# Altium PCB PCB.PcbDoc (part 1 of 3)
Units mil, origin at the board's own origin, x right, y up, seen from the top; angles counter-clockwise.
Board outline 3613 x 4415 mil, 2 copper layers (Top Layer, Bottom Layer), stack 62 mil thick; 332 components, 200 nets, 890 pads, 1069 vias.
Unrouted connection lines stored in the file: 1.
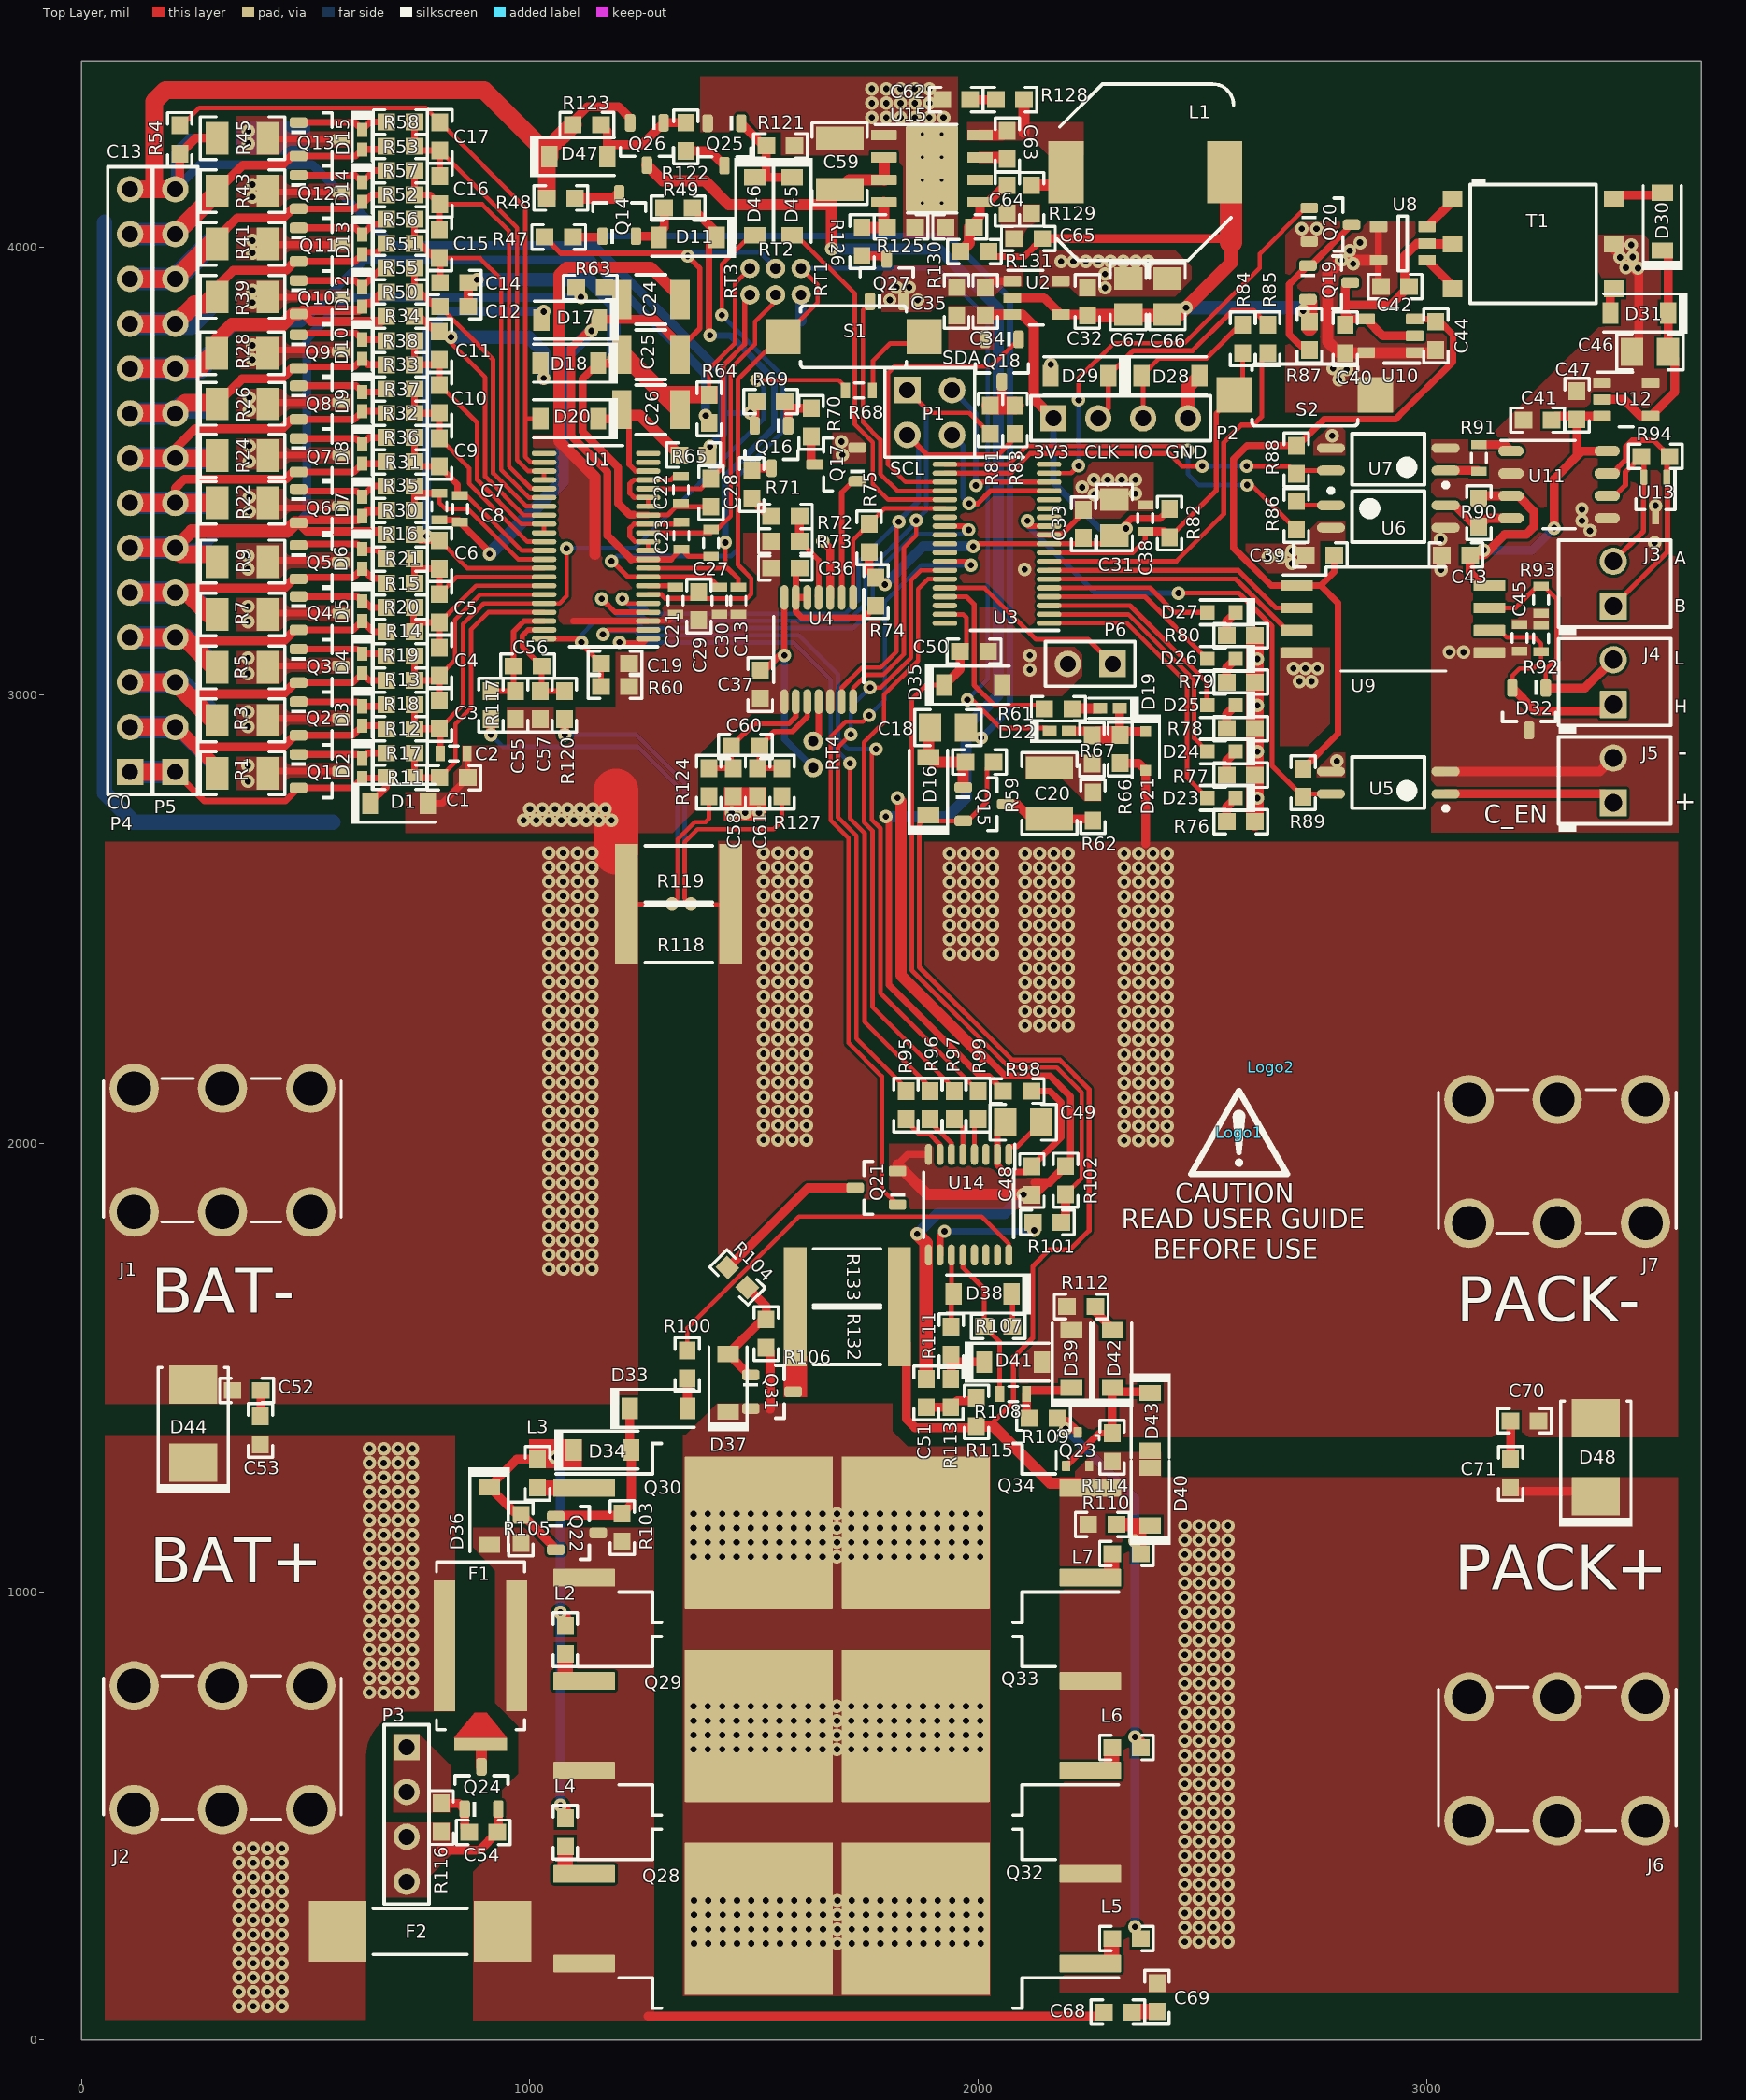
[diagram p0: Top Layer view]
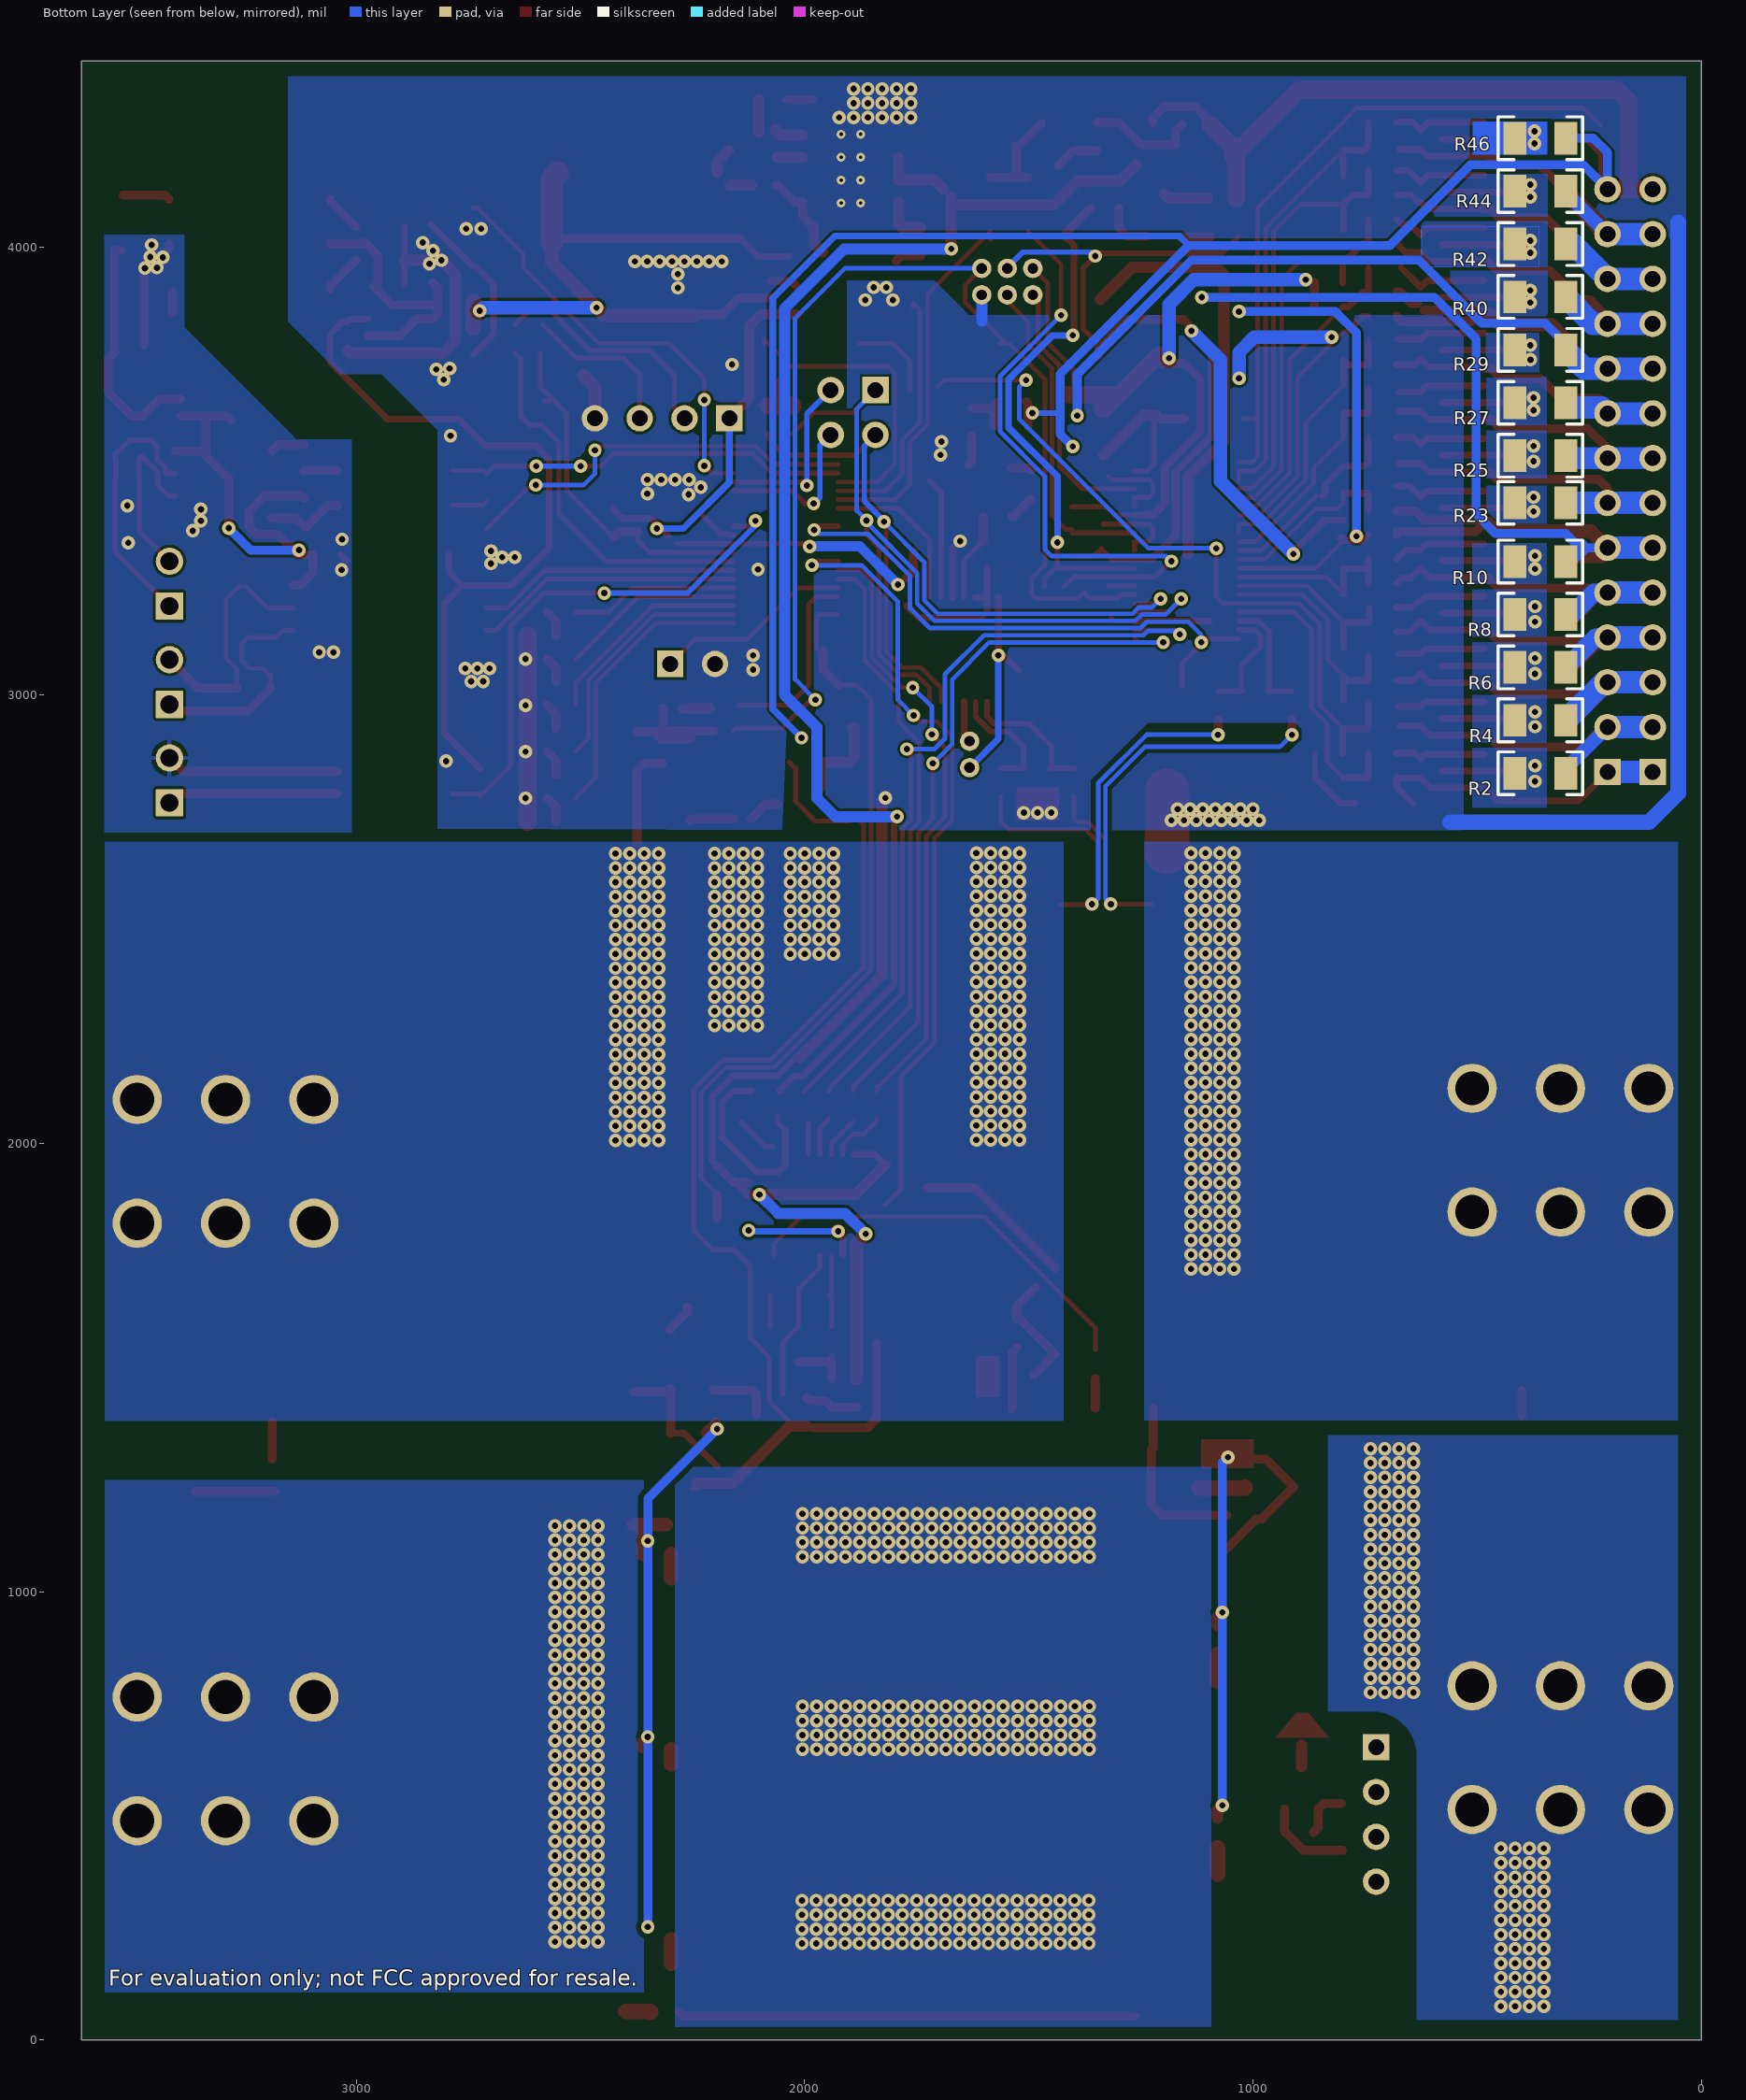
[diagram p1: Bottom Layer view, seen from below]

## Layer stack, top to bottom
Top Solder: solder mask 0.4, Solder Resist, Dk 3.5
Top Layer: signal copper 1.4
Dielectric1: core 59.2, FR-4, Dk 4.8
Bottom Layer: signal copper 1.4
Bottom Solder: solder mask 0.4, Solder Resist, Dk 3.5

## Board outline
0,0 0,4415 3613,4415 3613,0

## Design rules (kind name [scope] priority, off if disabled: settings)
AcuteAngle [All] p1: minimum=4.50000000000000E+0001 checktracksonly=FALSE
AssemblyTestPointUsage [All] p1: valid=2
BoardOutlineClearance BoardOutlineClearance_MountingHoles [OnCopper and InComponentClass('Mounting Holes')] p1: gap=10 ignorepadtopadclearanceinfootprint=FALSE
BoardOutlineClearance BoardOutlineClearance_Poly [OnCopper and IsPoly] p2: gap=10 ignorepadtopadclearanceinfootprint=FALSE
BoardOutlineClearance [OnCopper and Not InComponentClass('Logo') and not InComponentClass('FiducialMark') and not InRegion(1000,500,4000,800) and not InPoly] p3: gap=10 ignorepadtopadclearanceinfootprint=FALSE
Clearance Clearance_Keepouts [((IsTrack Or IsArc) And Not InPoly) And IsFree and IsKeepOut vs ((IsTrack Or IsArc) And Not InPoly) And IsFree and IsKeepOut] p1: gap=0 ignorepadtopadclearanceinfootprint=FALSE
Clearance Clearance_Poly [InPolygon] p2: gap=6 ignorepadtopadclearanceinfootprint=FALSE
Clearance Clearance_FiducialMark [IsKeepOut and InComponentClass('FiducialMark') vs IsPad and InComponentClass('FiducialMark')] p3: gap=0 ignorepadtopadclearanceinfootprint=FALSE
Clearance [All] p4: gap=6 ignorepadtopadclearanceinfootprint=FALSE except(12: Arc-Hole Track-Hole)
ComponentClearance ComponentClearance_MountingHoles_FiducialMarks [InComponentClass('Mounting Holes') vs InComponentClass('FiducialMark')] p1 off: gap=0 collisioncheckmode=3 verticalgap=10 showdistances=FALSE
ComponentClearance ComponentClearance_Shunt [InComponentClass('Header') vs InComponentClass('Shunt')] p2 off: gap=0 collisioncheckmode=3 verticalgap=0 showdistances=FALSE
ComponentClearance ComponentClearance_Logo [InComponentClass('Logo')] p3 off: gap=50 collisioncheckmode=3 verticalgap=10 showdistances=FALSE
ComponentClearance ComponentClearance_ScrewToNut [(HasFootprint('NY PMS 440 0025 PH')) vs (HasFootprint('Keystone_1902C'))] p4 off: gap=5 collisioncheckmode=3 verticalgap=10 showdistances=FALSE
ComponentClearance ComponentClearance_MountingHoles [InComponentClass('Mounting Holes')] p5 off: gap=250 collisioncheckmode=3 verticalgap=100000 showdistances=FALSE
ComponentClearance ComponentClearance_SmallPassives [HasFootprint('0201*') or HasFootprint('0402*') or HasFootprint('0508') or HasFootprint('0603*') or HasFootprint('0612') or HasFootprint('0805*') or HasFootprint('0815*') or HasFootprint('0830*') or HasFootprint('1206*') or HasFootprint('1210*') or HasFootprint('1808*') or HasFootprint('1812*') or HasFootprint('1825*') or HasFootprint('2010*') or HasFootprint('2220*') or HasFootprint('2225*') or HasFootprint('2512*') or HasFootprint('2728*') or HasFootprint('3518*') vs HasFootprint('0201*') or HasFootprint('0402*') or HasFootprint('0508') or HasFootprint('0603*') or HasFootprint('0612') or HasFootprint('0805*') or HasFootprint('0815*') or HasFootprint('0830*') or HasFootprint('1206*') or HasFootprint('1210*') or HasFootprint('1808*') or HasFootprint('1812*') or HasFootprint('1825*') or HasFootprint('2010*') or HasFootprint('2220*') or HasFootprint('2225*') or HasFootprint('2512*') or HasFootprint('2728*') or HasFootprint('3518*')] p6 off: gap=14.96 collisioncheckmode=3 verticalgap=10 showdistances=FALSE
ComponentClearance ComponentClearance_THtoSMT [IsThruComponent vs IsSMTComponent] p7 off: gap=40 collisioncheckmode=3 verticalgap=30 showdistances=FALSE
ComponentClearance ComponentClearance_THtoTH [IsThruComponent vs IsThruComponent] p8 off: gap=30 collisioncheckmode=3 verticalgap=30 showdistances=FALSE
ComponentClearance [All] p9 off: gap=0 collisioncheckmode=3 verticalgap=10 showdistances=FALSE
DiffPairsRouting [All] p1: maxlimit=100 minlimit=10 mostfreqgap=10 toplayer_minwidth=15 toplayer_maxwidth=15 toplayer_prefwidth=15 bottomlayer_minwidth=15 bottomlayer_maxwidth=15 bottomlayer_prefwidth=15 maxuncoupledlength=1000
FabricationTestPointUsage TestPointUsage [All] p1: valid=2 allowmultiple=FALSE
FabricationTestpoint Testpoint [All] p1: side=3 testpointundercomponent=TRUE minsize=40 maxsize=100 preferedsize=60 minholesize=0 maxholesize=40 preferedholesize=32 testpointgrid=1 allowsidetop=TRUE allowsidebottom=TRUE usegrid=TRUE gridtolerance=0.01
FanoutControl Fanout_LCC [IsLCC] p1: bgadir=Out bgaviamode=Centered fanoutstyle=Auto fanoutdirection=Alternating viagrid=1 // Fanout_LCC (Default Rule)
FanoutControl Fanout_BGA [IsBGA] p2: bgadir=Out bgaviamode=Centered fanoutstyle=Auto fanoutdirection=Alternating viagrid=1 // Fanout_BGA (Default Rule)
FanoutControl Fanout_Default [All] p4: bgadir=Out bgaviamode=Centered fanoutstyle=Auto fanoutdirection=Alternating viagrid=1 // Fanout_Default (Default Rule)
FanoutControl Fanout_Small [(CompPinCount < 5)] p5: bgadir=Out bgaviamode=Centered fanoutstyle=Auto fanoutdirection=OutThenIn viagrid=1 // Fanout_Small (Default Rule)
HoleSize [All] p1: absolutevalues=TRUE maxlimit=251 minlimit=7.87 maxpercent=80.000 minpercent=20.000
MinimumAnnularRing MinimumAnnularRing_ThermalPadVias [IsVia and InAnyComponent] p1: minimumring=5.91
MinimumAnnularRing [All] p2: minimumring=8
MinimumSolderMaskSliver MinimumSolderMaskSliver_Logo [InComponentClass('Logo') vs InComponentClass('Logo')] p1: minsoldermaskwidth=0.7
MinimumSolderMaskSliver [All] p2: minsoldermaskwidth=3.94
PlaneConnect [All] p1: planeconnectstyle=Relief reliefexpansion=10 reliefentries=4 reliefconductorwidth=10 reliefairgap=10
PolygonConnect [All] p1: connectstyle=Direct reliefconductorwidth=10 reliefentries=4 polygonreliefangle="90 Angle" airgapwidth=10
RoutingVias ThermalPadVias [IsVia and InAnyComponent] p1: holewidth=7.87 width=19.68 viastyle="Through Hole" minholewidth=7.87 minwidth=19.68 maxholewidth=12.99 maxwidth=23.62
RoutingVias [All] p2: holewidth=20 width=30 viastyle="Through Hole" minholewidth=7.87 minwidth=26 maxholewidth=40 maxwidth=65
SilkToBoardRegionClearance [Not ((IsComment or IsDesignator) And (Hide <> 'False')) and not InRegion(1000,500,4000,800)] p1:
SilkToSilkClearance SilkToSilkClearance_Pb-FreeLogo [(HasFootprint('Pb-Free_Overlay_Medium') OR HasFootprint('Pb-Free_Overlay_Small')) vs (HasFootprint('Pb-Free_Overlay_Medium') OR HasFootprint('Pb-Free_Overlay_Small'))] p1 off: silktosilkclearance=0
SilkToSilkClearance [All] p2 off: silktosilkclearance=4
SilkToSolderMaskClearance SilkToComponentPadClearance [(IsPad or IsFill or IsRegion) and InAnycomponent] p1 off: minsilkscreentomaskgap=5 clearancetoexposedcopper=TRUE
SilkToSolderMaskClearance "Silk to Solder Mask Opening" [All] p2 off: minsilkscreentomaskgap=4 clearancetoexposedcopper=FALSE
SolderMaskExpansion [All] p1: expansion=1.97
Width [All] p1: maxlimit=100 minlimit=8 preferedwidth=10 checkconnectedcopper=TRUE
15 further rules are at their usual default settings.

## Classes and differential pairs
component class Overview: C52 C53 C54 C55 C56 C57 C58 C59 C60 C61 C62 C63 C64 C65 C66 C67 C68 C69 C70 C71 D44 D45 D46 D47 D48 D49 F1 F2 J1 J2 J3 J4 J5 J6 J7 J9 L1 L2 L3 L4 L5 L6 L7 P3 P4 P5 P6 Q24 Q25 Q26 Q27 Q28 Q29 Q30 Q31 Q32 Q33 Q34 R116 R117 R118 R119 R120 R121 R122 R123 R124 R125 R126 R127 R128 R129 R130 R131 R132 R133 R135 R141 R143 U15
component class "U_Control and Gauge": C31 C32 C33 C34 C35 C36 C37 C38 C39 C40 C41 C42 C43 C44 C45 C46 C47 D23 D24 D25 D26 D27 D28 D29 D30 D31 D32 P1 P2 Q16 Q17 Q18 Q19 Q20 R69 R70 R71 R72 R73 R74 R75 R76 R77 R78 R79 R80 R81 R82 R83 R84 R85 R86 R87 R88 R89 R90 R91 R92 R93 R94 RT4 S2 T1 U2 U3 U4 U5 U6 U7 U8 U9 U10 U11 U12 U13
component class "U_FET Driver": C48 C49 C50 C51 D33 D34 D35 D36 D37 D38 D39 D40 D41 D42 D43 Q21 Q22 Q23 R95 R96 R97 R98 R99 R100 R101 R102 R103 R104 R105 R106 R107 R108 R109 R110 R111 R112 R113 R114 R115 U14
component class "U_Monitoring & CB": C1 C2 C3 C4 C5 C6 C7 C8 C9 C10 C11 C12 C13 C14 C15 C16 C17 C18 C19 C20 C21 C22 C23 C24 C25 C26 C27 C28 C29 C30 D1 D2 D3 D4 D5 D6 D7 D8 D9 D10 D11 D12 D13 D14 D15 D16 D17 D18 D19 D20 D21 D22 Q1 Q2 Q3 Q4 Q5 Q6 Q7 Q8 Q9 Q10 Q11 Q12 Q13 Q14 Q15 R1 R2 R3 R4 R5 R6 R7 R8 R9 R10 R11 R12 R13 R14 R15 R16 R17 R18 R19 R20 R21 R22 R23 R24 R25 R26 R27 R28 R29 R30 R31 R32 R33 R34 R35 R36 R37 R38 R39 R40 R41 R42 R43 R44 R45 R46 R47 R48 R49 R50 R51 R52 R53 R54 R55 R56 R57 R58 R59 R60 R61 R62 R63 R64 R65 R66 R67 R68 RT1 RT2 RT3 S1 U1
component class Designator: !PCB H4 Logo1 Logo2

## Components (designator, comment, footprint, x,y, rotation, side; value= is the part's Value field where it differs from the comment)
C1 "GRM188R71C105KE15D" 0603 830,2816 r0 top value=1uF
C2 "GRM188R71C105KE15D" 0603S 830,2870 r0 top value=1uF
C3 "GRM188R71C105KE15D" 0603 798,2957 r270 top value=1uF
C4 "GRM188R71C105KE15D" 0603 798,3075 r270 top value=1uF
C5 "GRM188R71C105KE15D" 0603 798,3194 r270 top value=1uF
C6 "GRM188R71C105KE15D" 0603 798,3314 r270 top value=1uF
C7 "GRM188R71C105KE15D" 0603S 798,3421 r270 top value=1uF
C8 "GRM188R71C105KE15D" 0603S 844,3416 r270 top value=1uF
C9 "GRM188R71C105KE15D" 0603 798,3542 r270 top value=1uF
C10 "GRM188R71C105KE15D" 0603 798,3661 r270 top value=1uF
C11 "GRM188R71C105KE15D" 0603 798,3780 r270 top value=1uF
C12 "GRM188R71C105KE15D" 0603 831,3867 r0 top value=1uF
C13 "C1608X7R1V105K080AC" 0603S 1465,3211 r270 top value=1uF
C14 "GRM188R71C105KE15D" 0603 831,3921 r0 top value=1uF
C15 "GRM188R71C105KE15D" 0603 798,4007 r270 top value=1uF
C16 "GRM188R71C105KE15D" 0603 799,4127 r270 top value=1uF
C17 "GRM188R71C105KE15D" 0603 799,4247 r270 top value=1uF
C18 "CGA4J2X7R2A104K125AA" 0805_HV 1933,2928 r0 top value=0.1uF
C19 "GCM1885C1H471JA16D" 0603 1190,3071 r0 top value=470pF
C20 "GRM32ER72A225KA35L" 1210_270 2159.02,2781 r270 top value=2.2uF
C21 "GRM188R71C105KE15D" 0603S 1325,3211 r270 top value=1uF
C22 "GRM188R71C105KE15D" 0603S 1337,3458 r270 top value=1uF
C23 "GRM188R71C105KE15D" 0603S 1338,3356 r270 top value=1uF
C24 "C3225X5R1H106K250AB" 1210_280 1270,3883 r180 top value=10uF
C25 "C3225X5R1H106K250AB" 1210_280 1270,3760 r180 top value=10uF
C26 "C3225X5R1H106K250AB" 1210_280 1270,3637 r180 top value=10uF
C27 "GCM188R71H472KA37D" 0603S 1404,3340 r270 top value=4700pF
C28 "GCM188R71H472KA37D" 0603 1404,3452 r270 top value=4700pF
C29 "GCM188R71H472KA37D" 0603 1377,3199 r270 top value=4700pF
C30 "GRM188R61C475KAAJ" 0603S 1423,3211 r270 top value=4.7uF
C31 "CL21B106KOQNNNE" 0805_HV 2304,3396.45 r270 top value=10uF
C32 "GRM188R71A225KE15D" 0603 2244,3878.63 r90 top value=2.2uF
C33 "GRM188R71C104KA01D" 0603 2235,3382.45 r270 top value=0.1uF
C34 "GRM188R61C475KAAJ" 0603 2015.77,3878.63 r90 top value=4.7uF
C35 "GRM188R61C475KAAJ" 0603 1952,3879 r90 top value=4.7uF
C36 "GRM188R71H104KA93D" 0603 1570,3284 r180 top value=0.1uF
C37 "GRM188R71C105KE15D" 0603 1514,3024 r270 top value=1uF
C38 "GRM1885C1H102JA01D" 0603S 2373,3395 r90 top value=1000pF
C39 "GRM188R71C104KA01D" 0603 2763,3313 r0 top value=0.1uF
C40 "GRM188R71A225KE15D" 0603 2819,3795 r270 top value=2.2uF
C41 "GRM188R71H104KA93D" 0603 3248,3614 r180 top value=0.1uF
C42 "GRM188R71C104KA01D" 0603 2930,3912 r180 top value=0.1uF
C43 "GRM188R71H104KA93D" 0603 3066,3313 r180 top value=0.1uF
C44 "GRM188R61C475KAAJ" 0603 3021,3802 r270 top value=4.7uF
C45 "GRM188R71H104KA93D" 0603S 3208,3128 r90 top value=0.1uF
C46 "CL21B106KOQNNNE" 0805_HV 3499,3766 r180 top value=10uF
C47 "GRM188R61C475KAAJ" 0603 3336,3647 r90 top value=4.7uF
C48 "GRM188R72A103KA01D" 0603 2119.9,1917.21 r270 top value=0.01uF
C49 "C2012X7R1V225K085AC" 0805_HV 2100.9,2047.21 r180 top value=2.2uF
C50 "GRM188R71H221KA01D" 0603 1991,3098 r0 top value=220pF
C51 "06031C222JAT2A" 0603 1884,1443 r90 top value=2200pF
C52 "GRM188R72A104KA35D" 0603 368,1449 r180 top value=0.1uF
C53 "GRM188R72A104KA35D" 0603 399,1360 r90 top value=0.1uF
C54 "GRM188R71H104KA93D" 0603 896,463 r0 top value=0.1uF
C55 "GRM188R71H104KA93D" 0603 968,2978 r270 top value=0.1uF
C56 "GRM188R71H104KA93D" 0603 995,3065 r180 top value=0.1uF
C57 "GRM188R71H104KA93D" 0603 1023,2978 r90 top value=0.1uF
C58 "GRM188R71H104KA93D" 0603 1453.6,2806 r270 top value=0.1uF
C59 "C3225X7S2A475K200AE" 1210 1691,4186 r90 top value=4.7uF
C60 "GRM188R71H104KA93D" 0603 1480.5,2886 r180 top value=0.1uF
C61 "GRM188R71H104KA93D" 0603 1508,2806 r90 top value=0.1uF
C62 "GRM1885C1H560JA01D" 0603 1951,4329 r180 top value=56pF
C63 "GRM1885C1H222JA01D" 0603 2065,4228 r90 top value=2200pF
C64 "GRM1885C1H560JA01D" 0603 2065,4106.5 r90 top value=56pF
C65 "GRM188R71H332KA01D" 0603 2112,4019 r0 top value=3300pF
C66 "GRM21BR71C475KA73L" 0805_HV 2422,3890 r90 top value=4.7uF
C67 "GRM21BR71C475KA73L" 0805_HV 2335,3890 r90 top value=4.7uF
C68 "GRM188R72A104KA35D" 0603 2312,62 r180 top value=0.1uF
C69 "GRM188R72A104KA35D" 0603 2399,95 r270 top value=0.1uF
C70 "GRM188R72A104KA35D" 0603 3219,1381 r0 top value=0.1uF
C71 "GRM188R72A104KA35D" 0603 3188,1264 r90 top value=0.1uF
D1 "MMSZ4685T1G" SOD-123 708,2759 r0 top value=3.6V
D2 "BZT52C5V6T-7" SOD-523 626,2836.91 r270 top value=5.6V
D3 "BZT52C5V6T-7" SOD-523 626,2953.8 r270 top value=5.6V
D4 "BZT52C5V6T-7" SOD-523 626,3070.7 r270 top value=5.6V
D5 "BZT52C5V6T-7" SOD-523 626,3187.59 r270 top value=5.6V
D6 "BZT52C5V6T-7" SOD-523 626,3304.49 r270 top value=5.6V
D7 "BZT52C5V6T-7" SOD-523 626,3421.38 r270 top value=5.6V
D8 "BZT52C5V6T-7" SOD-523 626,3538.28 r270 top value=5.6V
D9 "BZT52C5V6T-7" SOD-523 626,3655.18 r270 top value=5.6V
D10 "BZT52C5V6T-7" SOD-523 626,3772.07 r270 top value=5.6V
D11 "1N4148W-7-F" SOD-123 1352,4022 r180 top value=100V
D12 "BZT52C5V6T-7" SOD-523 626,3888.97 r270 top value=5.6V
D13 "BZT52C5V6T-7" SOD-523 626,4005.86 r270 top value=5.6V
D14 "BZT52C5V6T-7" SOD-523 626,4122.76 r270 top value=5.6V
D15 "BZT52C5V6T-7" SOD-523 626,4239.65 r270 top value=5.6V
D16 "MMSZ5248B-7-F" SOD-123 1889.02,2797 r90 top value=18V
D17 "1N4148W-7-F" SOD-123 1090,3837 r180 top value=100V
D18 "1N4148W-7-F" SOD-123 1088,3741 r180 top value=100V
D19 "SBR0220T5-7" SOD-523 2294,2971 r180 top value=20V
D20 "1N4148W-7-F" SOD-123 1088,3617 r180 top value=100V
D21 "MMSZ5226BS-7-F" SOD-323 2374,2876 r270 top value=3.3V
D22 "SBR0220T5-7" SOD-523 2181,2920 r0 top value=20V
D23 "150060RS75000" WL-SMCW_RED 2543,2771 r180 top value=Red
D24 "150060RS75000" WL-SMCW_RED 2543,2874.5 r180 top value=Red
D25 "150060RS75000" WL-SMCW_RED 2543,2978 r180 top value=Red
D26 "150060RS75000" WL-SMCW_RED 2543,3081.5 r180 top value=Red
D27 "150060RS75000" WL-SMCW_RED 2543,3185 r180 top value=Red
D28 "MMSZ4685T1G" SOD-123 2429,3713 r0 top value=3.6V
D29 "MMSZ4685T1G" SOD-123 2226,3713 r180 top value=3.6V
D30 "MBR0520LT1G" SOD-123 3526,4057 r90 top value=20V
D31 "MBR0520LT1G" SOD-123 3475,3853 r180 top value=20V
D32 "NUP3105LT1G" SOT-23 3229,2969 r270 top value=24V
D33 "BAT46W-7-F" SOD-123 1287,1409 r0 top value=100V
D34 "MMSZ5231B-7-F" SOD-123 1162,1316 r0 top value=5.1V
D35 "MMSZ4685T1G" SOD-123 1989,3022.59 r0 top value=3.6V
D36 "MMSZ5246B-7-F" SOD-123 909,1169 r270 top value=16V
D37 "MMSZ5246B-7-F" SOD-123 1442,1466 r90 top value=16V
D38 "MMSZ5248B-7-F" SOD-123 2010,1664 r180 top value=18V
D39 "BAT46W-7-F" SOD-123 2208,1519 r90 top value=100V
D40 "MMSZ5246B-7-F" SOD-123 2384,1212 r90 top value=16V
D41 "BAT46W-7-F" SOD-123 2078,1512 r0 top value=100V
D42 "1N4148W-7-F" SOD-123 2300,1519.01 r90 top value=100V
D43 "MMSZ5246B-7-F" SOD-123 2384,1379 r270 top value=16V
D44 "N/A" SMB 249,1375 r90 top value=60V
D45 "MBR0520LT1G" SOD-123 1585,4091 r270 top value=20V
D46 "MBR0520LT1G" SOD-123 1502,4091 r270 top value=20V
D47 "MMSZ5246B-7-F" SOD-123 1108,4202 r0 top value=16V
D48 "SMBJ60A-13-F" SMB 3378,1300 r90 top value=60V
F1 "CLM3820P5030C" FUSE_SFK-xx30x 890,879 r90 top
F2 "0456030.ER" FUSE_0456030 755,242 r180 top
J1 "BAT-" SCREW_TERMINAL_8199 314,1985 r0 top
J2 "BAT+" SCREW_TERMINAL_8199 314,652 r0 top
J3 "22-23-2021" Molex_22-23-2021 3417,3249 r90 top
J4 "22-23-2021" Molex_22-23-2021 3417,3029.5 r90 top
J5 "22-23-2021" Molex_22-23-2021 3417,2810 r90 top
J6 "Pack+" SCREW_TERMINAL_8199 3292,627 r0 top
J7 "Pack-" SCREW_TERMINAL_8199 3292,1960 r0 top
L1 "7447713680" WE-PD_1030 2373,4167 r0 top value=68uH
L2 "74279265" 0603 1079,893 r270 top value="600 ohm"
L3 "74279265" 0603 1017,1264 r270 top value="600 ohm"
L4 "74279265" 0603 1079,463 r270 top value="600 ohm"
L5 "74279265" 0603 2331,226 r0 top value="600 ohm"
L6 "74279265" 0603 2331,652 r0 top value="600 ohm"
L7 "74279265" 0603 2331,1085 r0 top value="600 ohm"
Logo1 "CAUTION.  READ USER GUIDE BEFORE USE" IEC_Caution_Small 2582,2025 r0 top
Logo2 "FCC disclaimer" FCC_disclaimer 2653,2171 r0 top
P1 "Header 2X2" HDR2X2 1842,3681 r270 top
P2 "Header 4" HDR1X4 2168,3618 r0 top
P3 "Header 4" HDR1X4 725,653 r270 top
P4 "Header 14" HDR1X14 108,2829 r90 top
P5 "Header 14" HDR1X14 209,2829 r90 top
P6 "Header 2" HDR1X2 2300,3070 r180 top
Q1 "DMG2302UK-7" SOT-23 531.24,2830.67 r0 top value=20V
Q2 "DMG2302UK-7" SOT-23 531.24,2948.15 r0 top value=20V
Q3 "DMG2302UK-7" SOT-23 531.24,3065.63 r0 top value=20V
Q4 "DMG2302UK-7" SOT-23 531.24,3183.1 r0 top value=20V
Q5 "DMG2302UK-7" SOT-23 531,3297 r0 top value=20V
Q6 "DMG2302UK-7" SOT-23 531,3422 r0 top value=20V
Q7 "DMG2302UK-7" SOT-23 531.24,3535.54 r0 top value=20V
Q8 "DMG2302UK-7" SOT-23 531.24,3653.01 r0 top value=20V
Q9 "DMG2302UK-7" SOT-23 531,3767 r0 top value=20V
Q10 "DMG2302UK-7" SOT-23 531.24,3887.97 r0 top value=20V
Q11 "DMG2302UK-7" SOT-23 531.24,4005.45 r0 top value=20V
Q12 "DMG2302UK-7" SOT-23 531.24,4122.92 r0 top value=20V
Q13 "DMG2302UK-7" SOT-23 531.24,4240.4 r0 top value=20V
Q14 "BSS123" SOT-23 1199.31,4071.42 r90 top value=100V
Q15 "ZXMP10A13FTA" SOT-23 2014.02,2757 r0 top value=-100V
Q16 "ZXMP10A13FTA" SOT-23 1539,3554 r270 top value=-100V
Q17 "BSS123" SOT-23 1683,3515 r180 top value=100V
Q18 "FDN302P" SOT-23 2053,3747 r270 top value=-20V
Q19 "FDN302P" SOT-23 2783,3921 r0 top value=-20V
Q20 "2N7002" SOT-23 2786,4050 r0 top value=60V
Q21 "BSS123" SOT-23 1773,1901 r180 top value=100V
Q22 "BSS84-7-F" SOT-23 1105,1131 r0 top value=-50V
Q23 "2N7002W-7-F" SOT-323 2222,1318 r90 top value=60V
Q24 "BSS123" SOT-23 892,562 r90 top value=100V
Q25 "BSS123" SOT-23 1434,4229 r270 top value=100V
Q26 "ZXMP10A13FTA" SOT-23 1261,4230 r270 top value=-100V
Q27 "2N7002" SOT-23 1796,3926 r90 top value=60V
Q28 "CSD19536KTT" KTT0002A_N 1363.21,270.21 r0 top value=100V
Q29 "CSD19536KTT" KTT0002A_N 1363.21,700.71 r0 top value=100V
Q30 "CSD19536KTT" KTT0002A_N 1363.21,1131.21 r0 top value=100V
Q31 "ZXMP10A13FTA" SOT-23 1540,1446 r0 top value=-100V
Q32 "CSD19536KTT" KTT0002A_N 2008.21,270.21 r180 top value=100V
Q33 "CSD19536KTT" KTT0002A_N 2008.21,700.71 r180 top value=100V
Q34 "CSD19536KTT" KTT0002A_N 2008.21,1131.21 r180 top value=100V
R1 "CRCW120680R6FKEA" 1206 358.91,2826 r180 top value=80.6
R2 "CRCW120680R6FKEA" 1206 358.91,2826 r180 bottom value=80.6
R3 "CRCW120680R6FKEA" 1206 358.91,2944.08 r180 top value=80.6
R4 "CRCW120680R6FKEA" 1206 358.91,2944.08 r180 bottom value=80.6
R5 "CRCW120680R6FKEA" 1206 358.91,3062.17 r180 top value=80.6
R6 "CRCW120680R6FKEA" 1206 358.91,3062.17 r180 bottom value=80.6
R7 "CRCW120680R6FKEA" 1206 358.91,3180.25 r180 top value=80.6
R8 "CRCW120680R6FKEA" 1206 358.91,3180.25 r180 bottom value=80.6
R9 "CRCW120680R6FKEA" 1206 358.91,3298.33 r180 top value=80.6
R10 "CRCW120680R6FKEA" 1206 358.91,3298.33 r180 bottom value=80.6
R11 "CRCW06031K00FKEA" 0603 711.01,2816.91 r0 top value=1.00k
R12 "CRCW06031K00FKEA" 0603 711.01,2925.2 r0 top value=1.00k
R13 "CRCW06031K00FKEA" 0603 711.01,3033.5 r0 top value=1.00k
R14 "CRCW06031K00FKEA" 0603 711.01,3141.8 r0 top value=1.00k
R15 "CRCW06031K00FKEA" 0603 711.01,3250.09 r0 top value=1.00k
R16 "CRCW06031K00FKEA" 0603 711.01,3358.39 r0 top value=1.00k
R17 "CRCW060310K0JNEA" 0603 711.01,2871.05 r0 top value=10k
R18 "CRCW060310K0JNEA" 0603 711.01,2979.35 r0 top value=10k
R19 "CRCW060310K0JNEA" 0603 711.01,3087.65 r0 top value=10k
R20 "CRCW060310K0JNEA" 0603 711.01,3195.94 r0 top value=10k
R21 "CRCW060310K0JNEA" 0603 711.01,3304.24 r0 top value=10k
R22 "CRCW120680R6FKEA" 1206 358.91,3429.42 r180 top value=80.6
R23 "CRCW120680R6FKEA" 1206 358.91,3429.42 r180 bottom value=80.6
R24 "CRCW120680R6FKEA" 1206 358.91,3534.5 r180 top value=80.6
R25 "CRCW120680R6FKEA" 1206 358.91,3534.5 r180 bottom value=80.6
R26 "CRCW120680R6FKEA" 1206 359,3650 r180 top value=80.6
R27 "CRCW120680R6FKEA" 1206 358.91,3652.58 r180 bottom value=80.6
R28 "CRCW120680R6FKEA" 1206 358,3763 r180 top value=80.6
R29 "CRCW120680R6FKEA" 1206 358.91,3770.67 r180 bottom value=80.6
R30 "CRCW06031K00FKEA" 0603 711.01,3412.54 r0 top value=1.00k
R31 "CRCW06031K00FKEA" 0603 711.01,3520.83 r0 top value=1.00k
R32 "CRCW06031K00FKEA" 0603 711.01,3629.13 r0 top value=1.00k
R33 "CRCW06031K00FKEA" 0603 711.01,3737.42 r0 top value=1.00k
R34 "CRCW06031K00FKEA" 0603 711.01,3845.72 r0 top value=1.00k
R35 "CRCW060310K0JNEA" 0603 711.01,3466.68 r0 top value=10k
R36 "CRCW060310K0JNEA" 0603 711.01,3574.98 r0 top value=10k
R37 "CRCW060310K0JNEA" 0603 711.01,3683.28 r0 top value=10k
R38 "CRCW060310K0JNEA" 0603 711.01,3791.57 r0 top value=10k
R39 "CRCW120680R6FKEA" 1206 358.91,3888.75 r180 top value=80.6
R40 "CRCW120680R6FKEA" 1206 358.91,3888.75 r180 bottom value=80.6
R41 "CRCW120680R6FKEA" 1206 358.91,4006.83 r180 top value=80.6
R42 "CRCW120680R6FKEA" 1206 358.91,4006.83 r180 bottom value=80.6
R43 "CRCW120680R6FKEA" 1206 358.91,4124.92 r180 top value=80.6
R44 "CRCW120680R6FKEA" 1206 358.91,4124.92 r180 bottom value=80.6
R45 "CRCW120680R6FKEA" 1206 358.91,4243 r180 top value=80.6
R46 "CRCW120680R6FKEA" 1206 358.91,4243 r180 bottom value=80.6
R47 "CRCW0603100KFKEA" 0603 1064.31,4022.42 r0 top value=100k
R48 "CRCW0603200RFKEA" 0603 1069.31,4109.42 r0 top value=200
R49 "CRCW0603100KFKEA" 0603 1331,4087 r0 top value=100k
R50 "CRCW06031K00FKEA" 0603 711.01,3899.87 r0 top value=1.00k
R51 "CRCW06031K00FKEA" 0603 711.01,4008.16 r0 top value=1.00k
R52 "CRCW06031K00FKEA" 0603 711.01,4116.46 r0 top value=1.00k
R53 "CRCW06031K00FKEA" 0603 711.01,4224.76 r0 top value=1.00k
R54 "CRCW06031K00FKEA" 0603 219,4240 r90 top value=1.00k
R55 "CRCW060310K0JNEA" 0603 711.01,3954.02 r0 top value=10k
R56 "CRCW060310K0JNEA" 0603 711.01,4062.31 r0 top value=10k
R57 "CRCW060310K0JNEA" 0603 711.01,4170.61 r0 top value=10k
R58 "CRCW060310K0JNEA" 0603 711.01,4278.91 r0 top value=10k
R59 "CRCW06031M00JNEA" 0603 2003.02,2851 r0 top value=1.0Meg
R60 "CRCW0603499KFKEA" 0603 1190,3020 r180 top value=499k
R61 "CRCW0603100RFKEA" 0603 2179,2970 r180 top value=100
R62 "CRCW060310M0JNEA" 0603 2256,2752 r90 top value=10Meg
R63 "CRCW06031K00FKEA" 0603 1135,3910 r0 top value=1.00k
R64 "CRCW06031K00FKEA" 0603 1400,3639 r90 top value=1.00k
R65 "CRCW06031K00FKEA" 0603 1365,3536 r180 top value=1.00k
R66 "CRCW060310K0JNEA" 0603 2317,2880 r90 top value=10k
R67 "ERJ-3EKF3603V" 0603 2254,2879 r270 top value=360k
R68 "CRCW06033K01FKEA" 0603S 1734,3680 r180 top value=3.01k
R69 "CRCW06031M00JNEA" 0603 1537,3655 r0 top value=1.0Meg
R70 "CRCW06033M30JNEA" 0603 1627.4,3609.03 r270 top value=3.3Meg
R71 "RT0603BRD07505KL" 0603 1495,3470 r270 top value=505k
R72 "RT0603BRD07505KL" 0603 1570,3399 r0 top value=505k
R73 "RT0603BRD0716K5L" 0603 1570,3344 r0 top value=16.5k
R74 "RC0603FR-0747RL" 0603 1772,3231 r270 top value=47.0
R75 "CRCW060310K0FKEA" 0603 1757,3351 r90 top value=10.0k
R76 "RC0603FR-07470RL" 0603 2586,2718 r180 top value=470
R77 "RC0603FR-07470RL" 0603 2586,2821.75 r180 top value=470
R78 "RC0603FR-07470RL" 0603 2586,2925.5 r180 top value=470
R79 "RC0603FR-07470RL" 0603 2586,3029.25 r180 top value=470
R80 "RC0603FR-07470RL" 0603 2586,3133 r180 top value=470
R81 "CRCW060310K0FKEA" 0603 2027.16,3614.59 r270 top value=10.0k
R82 "RC0603FR-0747KL" 0603 2427,3384 r90 top value=47.0k
R83 "CRCW060310K0FKEA" 0603 2082.16,3614.59 r270 top value=10.0k
R84 "CRCW0603100RFKEA" 0603 2590,3795 r90 top value=100
R85 "CRCW0603100RFKEA" 0603 2646,3795 r90 top value=100
R86 "CRCW06036K80JNEA" 0603 2709.93,3401.5 r270 top value=6.8k
R87 "CRCW0603100KFKEA" 0603 2739,3802 r270 top value=100k
R88 "CRCW060310K0FKEA" 0603 2710,3525.5 r90 top value=10.0k
R89 "CRCW060310K0FKEA" 0603 2725,2805 r90 top value=10.0k
R90 "CRCW060310K0FKEA" 0603 3117,3407.5 r90 top value=10.0k
R91 "CRCW060310K0FKEA" 0603S 3117,3529.5 r90 top value=10.0k
R92 "RC0603FR-0760R4L" 0603S 3256,3127 r270 top value=60.4
R93 "RC0603FR-0760R4L" 0603S 3256,3213 r270 top value=60.4
R94 "RC0603FR-07120RL" 0603 3511,3533 r180 top value=120
R95 "CRCW06031K00FKEA" 0603 1839.4,2085.45 r270 top value=1.00k
R96 "CRCW06031K00FKEA" 0603 1892.9,2085.45 r270 top value=1.00k
R97 "CRCW06031K00FKEA" 0603 1946.4,2085.45 r270 top value=1.00k
R98 "CRCW0603100RFKEA" 0603 2087,2117 r180 top value=100
R99 "CRCW06031K00FKEA" 0603 1999.9,2085.45 r270 top value=1.00k
R100 "CRCW0603200RFKEA" 0603 1351,1507 r270 top value=200
R101 "RT0603BRD07665KL" 0603 2154,1824 r0 top value=665k
R102 "RT0603BRD0716K5L" 0603 2195,1918 r270 top value=16.5k
R103 "CRCW060310M0JNEA" 0603 1206,1143 r270 top value=10Meg
R104 "CRCW06033M30JNEA" 0603 1463,1701 r315 top value=3.3Meg
R105 "CRCW060310M0JNEA" 0603 980,1140 r270 top value=10Meg
R106 "CRCW06031M00JNEA" 0603 1527,1576 r270 top value=1.0Meg
R107 "CRCW0603100RFKEA" 0603 2045,1592 r180 top value=100
R108 "CRCW0603100RFKEA" 0603S 2078,1441 r0 top value=100
R109 "CRCW0603510RJNEA" 0603 2146,1387 r0 top value=510
R110 "CRCW060310M0JNEA" 0603 2277,1150 r180 top value=10Meg
R111 "CRCW0603100RFKEA" 0603 1940,1560 r270 top value=100
R112 "CRCW06031M00JNEA" 0603 2230,1636 r0 top value=1.0Meg
R113 "CRCW0603100RFKEA" 0603 1939,1443 r270 top value=100
R114 "CRCW060310M0JNEA" 0603 2299,1322 r90 top value=10Meg
R115 "RC0603FR-0747RL" 0603 1996,1401 r270 top value=47.0
R116 "CRCW06032M49FKEA" 0603 802,496 r90 top value=2.49Meg
R117 "CRCW0603100RFKEA" 0603 913.07,2978 r90 top value=100
R118 "CSNL2512FT2L00" 2512 1332,2467 r0 top value=0.002
R119 "CSNL2512FT2L00" 2512 1332,2601 r0 top value=0.002
R120 "CRCW0603100RFKEA" 0603 1077,2978 r90 top value=100
R121 "CRCW060310M0JNEA" 0603 1559,4226 r180 top value=10Meg
R122 "CRCW06036M80JNEA" 0603 1348,4246 r90 top value=6.8Meg
R123 "CRCW06033M00JNEA" 0603 1127,4273 r180 top value=3.0Meg
R124 "CRCW0603100RFKEA" 0603 1399.33,2806 r90 top value=100
R125 "CRCW06031M00FKEA" 0603 1828,4045 r0 top value=1.00Meg
R126 "CRCW0603115KFKEA" 0603 1741,4012 r270 top value=115k
R127 "CRCW0603100RFKEA" 0603 1562.33,2806 r90 top value=100
R128 "RC0603FR-07383KL" 0603 2071,4329 r0 top value=383k
R129 "RC0603FR-07383KL" 0603 2119,4106.5 r270 top value=383k
R130 "CRCW0603240KJNEA" 0603 1959,4045 r0 top value=240k
R131 "CRCW0603715KFKEA" 0603 1992,3990 r0 top value=715k
R132 "CRCW2512604RFKEG" 2512 1708,1570 r180 top value=604
R133 "CRCW2512604RFKEG" 2512 1708,1702 r180 top value=604
RT1 "NTCALUG03A103G" NTCALUG03 1605,3923 r180 top value="10k ohm"
RT2 "NTCALUG03A103G" NTCALUG03 1548,3923 r180 top value="10k ohm"
RT3 "NTCALUG03A103G" NTCALUG03 1491,3923 r180 top value="10k ohm"
RT4 "NTCALUG03A103G" NTCALUG03 1632,2868 r0 top value="10k ohm"
S1 "RS-032G05A3-SM RT" SW_RS-032G05A3-SM 1722,3800 r0 top
S2 "RS-032G05A3-SM RT" SW_RS-032G05A3-SM 2729,3670 r0 top
T1 "760390012" Wurth_760390012 3238.32,4007 r0 top value=475uH
U1 "BQ7694003DBTR" DBT0044A_N 1147.83,3332.87 r180 top
U2 "TLV70433DBVR" DBV0005A_N 2130.13,3887 r0 top
U3 "MSP430FR2155TDBTR" DBT0038A_N 2042,3338 r180 top
U4 "BQ34Z100PWR-G1" PW0014A_N 1644.4,3102.03 r270 top
U5 "TLP293(GB-TPL,E" SO4 2915,2805 r180 top
U6 "TLP293(GB-TPL,E" SO4 2915,3399 r0 top
U7 "TLP293(GB-TPL,E" SO4 2915,3526.5 r180 top
U8 "SN6501DBVR" DBV0005A_N 2947.32,4008 r180 top
U9 "ISO1042BDWVR" DWV0008A 2926,3170 r0 top
U10 "TLV70433DBVR" DBV0005A_N 2920,3802 r180 top
U11 "THVD1500DR" D0008A_N 3296,3470 r0 top
U12 "TLV70450DBVT" DBV0005A_N 3446,3660 r0 top
U13 "TPD2E007DCKR" DCK0003A_N 3511,3442 r270 top
U14 "BQ76200PWR" PW0016A_L 1978.9,1863.21 r270 top
U15 "LM5164DDAT" DDA0008E_N 1897,4175 r0 top

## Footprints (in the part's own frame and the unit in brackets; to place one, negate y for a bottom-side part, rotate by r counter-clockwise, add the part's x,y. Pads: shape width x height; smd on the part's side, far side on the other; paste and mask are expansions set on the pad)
0603 [mm] "0603 from SM-752 data"
  rect 1x0.95 smd: 1(-0.8,0) 2(0.8,0)
  silkscreen extent -1.52,-0.69 1.52,0.69, body extent -0.87,-0.47 0.87,0.47, height 1
0603S [mil] "0603 from SM-752 data"
  rect 20x35 smd: 1(-30,0) 2(30,0)
  silkscreen extent -10,-17 10,17, body extent -34,-19 34,19, height 39
0805_HV [mil] "0805 with 30mil clearance between pads"
  rect 50x63 smd: 1(-40,0) 2(40,0)
  silkscreen extent -74,-40 74,40, body extent -43,-29 43,29, height 57
1206 [mm] "1206 from SM-752 data"
  rect 1.3x1.85 smd: 1(-1.45,0) 2(1.45,0)
  silkscreen extent -2.4,-1.21 2.4,1.21, body extent -1.7,-0.9 1.7,0.9, height 1.35
1210 [mm] "1210 from SM-752 data"
  rect 1.3x2.7 smd: 1(-1.45,0) 2(1.45,0)
  silkscreen extent -2.32,-1.57 2.32,1.57, body extent -1.7,-1.35 1.7,1.35, height 1.35
1210_270 [mm] "1210"
  rect 1.3x2.7 smd: 1(-1.45,0) 2(1.45,0)
  silkscreen extent -2.32,-1.57 2.32,1.57, body extent -1.7,-1.35 1.7,1.35, height 2.7
1210_280 [mm] "SMD, 2-Leads, Body 3.6x2.8mm, Height 2.8mm"
  rect 1.1x2.2 smd: 1(-1.65,0) 2(1.65,0)
  silkscreen extent -0.84,-1.4 0.84,1.4, body extent -1.8,-1.4 1.8,1.4, height 2.8
2512 [mm] "Chip Resistor, Body 6.3x3.2mm, IPC Medium Density"
  rect 1.3x3.4 smd: 1(-2.95,0) 2(2.95,0)
  silkscreen extent -1.9,-1.6 1.9,1.6, body extent -3.22,-1.67 3.22,1.67, height 0.71
D0008A_N [mm] "SOIC, 8-Leads, Body 4.9x3.9mm, Pitch 1.27mm, IPC Medium Density"
  oval 1.45x0.6 smd: 1(-2.725,1.905) 2(-2.725,0.635) 3(-2.725,-0.635) 4(-2.725,-1.905) 5(2.725,-1.905) 6(2.725,-0.635) 7(2.725,0.635) 8(2.725,1.905)
  silkscreen extent -3.3,-2.5 0.9,2.5, body extent -3,-2.45 3,2.45, height 1.63
DBT0038A_N [mm] "TSSOP, 38-Leads, Body 9.7x4.4mm, Pitch 0.5mm, IPC Medium Density"
  oval 1.4x0.3 smd: 1(-2.95,4.5) 2(-2.95,4) 3(-2.95,3.5) 4(-2.95,3) 5(-2.95,2.5) 6(-2.95,2) 7(-2.95,1.5) 8(-2.95,1) 9(-2.95,0.5) 10(-2.95,0) 11(-2.95,-0.5) 12(-2.95,-1) 13(-2.95,-1.5) 14(-2.95,-2) 15(-2.95,-2.5) 16(-2.95,-3) 17(-2.95,-3.5) 18(-2.95,-4) 19(-2.95,-4.5) 20(2.95,-4.5) 21(2.95,-4) 22(2.95,-3.5) 23(2.95,-3) 24(2.95,-2.5) 25(2.95,-2) 26(2.95,-1.5) 27(2.95,-1) 28(2.95,-0.5) 29(2.95,0) 30(2.95,0.5) 31(2.95,1) 32(2.95,1.5) 33(2.95,2) 34(2.95,2.5) 35(2.95,3) 36(2.95,3.5) 37(2.95,4) 38(2.95,4.5)
  silkscreen extent -3.5,-4.9 1.5,4.9, body extent -3.21,-4.85 3.21,4.85, height 1.2
DBT0044A_N [mm] "TSSOP, 44-Leads, Body 11.3x4.4mm, Pitch 0.5mm, IPC Medium Density"
  oval 1.4x0.3 smd: 1(-2.95,5.25) 2(-2.95,4.75) 3(-2.95,4.25) 4(-2.95,3.75) 5(-2.95,3.25) 6(-2.95,2.75) 7(-2.95,2.25) 8(-2.95,1.75) 9(-2.95,1.25) 10(-2.95,0.75) 11(-2.95,0.25) 12(-2.95,-0.25) 13(-2.95,-0.75) 14(-2.95,-1.25) 15(-2.95,-1.75) 16(-2.95,-2.25) 17(-2.95,-2.75) 18(-2.95,-3.25) 19(-2.95,-3.75) 20(-2.95,-4.25) 21(-2.95,-4.75) 22(-2.95,-5.25) 23(2.95,-5.25) 24(2.95,-4.75) 25(2.95,-4.25) 26(2.95,-3.75) 27(2.95,-3.25) 28(2.95,-2.75) 29(2.95,-2.25) 30(2.95,-1.75) 31(2.95,-1.25) 32(2.95,-0.75) 33(2.95,-0.25) 34(2.95,0.25) 35(2.95,0.75) 36(2.95,1.25) 37(2.95,1.75) 38(2.95,2.25) 39(2.95,2.75) 40(2.95,3.25) 41(2.95,3.75) 42(2.95,4.25) 43(2.95,4.75) 44(2.95,5.25)
  silkscreen extent -3.47,-5.7 1.5,5.7, body extent -3.21,-5.57 3.21,5.58, height 1.2
DBV0005A_N [mm] "SOT23, 5-Leads, Body 2.9x1.6mm, Pitch 0.95mm, Lead Span 2.8mm, IPC Medium Density"
  rrect17% 1x0.6 smd: 1(-1.375,0.95) 2(-1.375,0) 3(-1.375,-0.95) 4(1.375,-0.95) 5(1.375,0.95)
  silkscreen extent -1.63,-1.55 0.38,1.55, body extent -1.42,-1.46 1.42,1.46, height 1.09
DCK0003A_N [mm] "SOT23, 3-Leads, Body 2.0x1.25mm, Pitch 0.65mm, Lead Span 2.1mm, IPC Medium Density"
  rrect25% 0.85x0.4 smd: 1(-1.125,0.65) 2(-1.125,-0.65) 3(1.125,0)
  silkscreen extent -1.48,-1.1 0.7,1.1, body extent -1.06,-1 1.06,1, height 1.1
DDA0008E_N [mm]
  rrect17% 1.45x0.6 smd: 1(-2.725,1.905) 2(-2.725,0.635) 3(-2.725,-0.635) 4(-2.725,-1.905) 5(2.725,-1.905) 6(2.725,-0.635) 7(2.725,0.635) 8(2.725,1.905)
  rrect7% 2.95x4.9 smd paste-1.5 mask-1.5: 9(0,0)
  rrect4% 2.4x3.1 on Top Paste: 9(0,0)
  rrect4% 2.4x3.1 on Top Solder: 9(0,0)
  silkscreen extent -3.22,-2.5 1.4,2.5, body extent -3,-2.45 3,2.45, height 1.57
DWV0008A [mm] "SOIC, 8-Leads, Body 5.95x7.6mm (max), Pitch 1.27mm"
  rrect17% 1.8x0.6 smd: 1(-5.45,1.905) 2(-5.45,0.635) 3(-5.45,-0.635) 4(-5.45,-1.905) 5(5.45,-1.905) 6(5.45,-0.635) 7(5.45,0.635) 8(5.45,1.905)
  silkscreen extent -6.25,-2.95 2.98,2.95, body extent -5.77,-2.92 5.77,2.93, height 2.67
FCC_disclaimer [mil]
FUSE_0456030 [mm] "SMD, 2-Leads, Body 10.1x3.12mm"
  rect 3.25x3.43 smd: 1(-4.675,0) 2(4.675,0)
  silkscreen extent -2.65,-1.3 2.65,1.3, body extent -5.05,-1.56 5.05,1.56, height 3.12
FUSE_SFK-xx30x [mm] "Fuse"
  rect 7.4x1.2 smd paste+0 mask+0.07: 1(0,2.05) 3(0,-2.05)
  rect 0.75x3 smd paste+0 mask+0.07: 2(-5.575,0)
  Top Layer region: -5.2,1.5 -5.2,-1.5 -3.8,-0.35 -3.8,0.35
  silkscreen extent -4.75,-2.5 4.75,2.5, body extent -4.75,-2.5 4.75,2.5, height 2
HDR1X2 [mm] "Connector; Header; 2 Position"
  rect 1.5x1.5 hole 0.9: 1(0,0)
  round 1.5 hole 0.9: 2(2.54,0)
  silkscreen extent -1.27,-1.27 3.81,1.27
HDR1X4 [mm] "Connector; Header; 4 Position"
  rect 1.5x1.5 hole 0.9: 1(0,0)
  round 1.5 hole 0.9: 2(2.54,0) 3(5.08,0) 4(7.62,0)
  silkscreen extent -1.27,-1.27 8.89,1.27
HDR1X14 [mm] "Connector; Header; 14 Position"
  rect 1.5x1.5 hole 0.9: 1(0,0)
  round 1.5 hole 0.9: 2(2.54,0) 3(5.08,0) 4(7.62,0) 5(10.16,0) 6(12.7,0) 7(15.24,0) 8(17.78,0) 9(20.32,0) 10(22.86,0) 11(25.4,0) 12(27.94,0) 13(30.48,0) 14(33.02,0)
  silkscreen extent -1.27,-1.27 34.29,1.27
HDR2X2 [mm] "Connector; Header; 2x2 Position"
  rect 1.5x1.5 hole 0.9: 1(0,0)
  round 1.5 hole 0.9: 2(0,2.54) 3(2.54,0) 4(2.54,2.54)
  silkscreen extent -1.27,-1.27 3.81,3.81
IEC_Caution_Small [mil]
  silkscreen extent -107,-93 107,92
KTT0002A_N [mm] "D2-PAK, 2-Leads, Body 9x10.1mm, Pitch 2.54mm, Lead Span 15.1mm, IPC Medium Density"
  rrect10% 3.5x1 smd: 1(-6.15,2.54) 3(-6.15,-2.54)
  rrect1% 8.4x8.65 smd paste-4.2: 2(3.75,0)
  silkscreen extent -7.75,-5.07 -1.78,5.07, body extent -6.68,-5.08 7.62,5.08, height 4.72
Molex_22-23-2021 [mm] "Header, 2.54mm, 2x1, TH"
  rrect6% 1.55x1.55 hole 1.02: 1(-1.27,0)
  round 1.55 hole 1.02: 2(1.27,0)
  silkscreen extent -2.92,-3.25 2.46,3.1, body extent -2.46,-3.25 2.46,3.1, height 10.08
NTCALUG03 [mm] "NTC Thermistor, Mini Lug Sensor, Pitch 1.5mm"
  round 1.1 hole 0.6: 1(0,0.75) 2(0,-0.75)
PW0014A_N [mm] "TSOP, 14-Leads, Body 5x4.4mm, Pitch 0.65mm, IPC Medium Density"
  oval 1.4x0.45 smd: 1(-2.95,1.95) 2(-2.95,1.3) 3(-2.95,0.65) 4(-2.95,0) 5(-2.95,-0.65) 6(-2.95,-1.3) 7(-2.95,-1.95) 8(2.95,-1.95) 9(2.95,-1.3) 10(2.95,-0.65) 11(2.95,0) 12(2.95,0.65) 13(2.95,1.3) 14(2.95,1.95)
  silkscreen extent -3.4,-2.55 1.85,2.55, body extent -3.21,-2.5 3.21,2.5, height 1
PW0016A_L [mm] "TSOP, 16-Leads, Body 5x4.4mm, Pitch 0.65mm, IPC High Density"
  oval 1.2x0.4 smd: 1(-2.85,2.275) 2(-2.85,1.625) 3(-2.85,0.975) 4(-2.85,0.325) 5(-2.85,-0.325) 6(-2.85,-0.975) 7(-2.85,-1.625) 8(-2.85,-2.275) 9(2.85,-2.275) 10(2.85,-1.625) 11(2.85,-0.975) 12(2.85,-0.325) 13(2.85,0.325) 14(2.85,0.975) 15(2.85,1.625) 16(2.85,2.275)
  silkscreen extent -2,-2.55 1.85,2.55, body extent -3.21,-2.5 3.21,2.5, height 1
SCREW_TERMINAL_8199 [mil] "Keystone Teminal, 30 Amp"
  round 110 hole 76: 1(-197,138) 2(0,138) 3(197,138) 4(197,-138) 5(0,-138) 6(-197,-138)
  silkscreen extent -265,-160 265,160, body extent -253,-177 254,177, height 325
SMB [mil] "Molded Diode, 2-Leads, Body 5.4x3.6mm, IPC Medium Density, based on OnSemi component dimensions"
  rect 85x107.99 smd: 1(-87.01,0) 2(87.01,0)
  silkscreen extent -155,-82 125,82, body extent -106,-71 106,71, height 91
SO4 [mm] "SOP, 4-Leads, Body 2.65x4.60mm, Pitch 1.27mm, IPC Medium Density"
  oval 1.6x0.55 smd: 1(-3.25,0.635) 2(-3.25,-0.635) 3(3.25,-0.635) 4(3.25,0.635)
  silkscreen extent -3.38,-1.45 2.05,1.58, body extent -2.4,-1.45 2.4,1.45, height 2.2
SOD-123 [mm] "On Semi recommended land pattern"
  rect 0.915x1.22 smd: 1(-1.637,0) 2(1.637,0)
  silkscreen extent -2.74,-1.17 2.03,1.17, body extent -1.93,-0.9 1.93,0.9, height 1.35
SOD-323 [mm] "NXP recommended land pattern"
  rect 0.6x0.6 smd paste-0.05: 1(-1.1,0) 2(1.1,0)
  silkscreen extent -2.06,-0.86 1.53,0.86, body extent -1.3,-0.67 1.3,0.68, height 1.1
SOD-523 [mm] "NXP Semiconductor recommended land pattern, nominal STEP model"
  rect 0.8x0.6 smd paste-0.05: 1(-0.55,0) 2(0.55,0)
  silkscreen extent -1.65,-0.66 1.2,0.66, body extent -0.8,-0.4 0.8,0.4, height 0.72
SOT-23 [mm] "SOT23, 3-Leads, Body 2.9x1.3mm, Pitch 0.95mm, Lead Span 2.5mm, IPC Medium Density"
  rrect50% 1x0.6 smd: 1(-1.2,0.95) 2(-1.2,-0.95) 3(1.2,0)
  silkscreen extent -1.63,-1.5 0.7,1.5, body extent -1.16,-1.45 1.21,1.45, height 1
SOT-323 [mm] "Diodes Inc recommended land pattern.  2016-02-24"
  rrect21% 0.6x0.47 smd: 1(-0.95,0.65) 2(-0.95,-0.65) 3(0.95,0)
  silkscreen extent -1.14,-1.22 0.77,1.22, body extent -1.13,-1.13 1.12,1.12, height 1.13
SW_RS-032G05A3-SM [mm] "SMT, 2-Leads, Body 6x3.5mm, Pin Spacing 8mm"
  rect 2x2 smd: 1(-4,0) 2(4,0)
  silkscreen extent -3,-1.75 3,1.75, body extent -4,-1.75 4,1.75, height 4.3
WE-PD_1030 [mm] "WERTH"
  rect 2x3.5 smd: 1(-4.5,0) 2(4.5,0)
  silkscreen extent -5,-5 5,5, body extent -5,-5 5,5, height 2.7
WL-SMCW_RED [mm] "WURTH"
  rect 0.8x0.8 smd: 1(-0.8,0) 2(0.8,0)
  silkscreen extent -1.9,-0.8 1.2,0.8, body extent -0.85,-0.45 0.85,0.45, height 0.8
Wurth_760390012 [mm] "SMD, 6-Leads, Body 7.14x6.73mm, Pitch 2.54mm"
  rect 1.12x0.96 smd: 1(-4.57,2.54) 2(-4.57,0) 3(-4.57,-2.54) 4(4.57,-2.54) 5(4.57,0) 6(4.57,2.54)
  silkscreen extent -3.57,-3.36 3.57,3.7, body extent -5.02,-3.36 5.02,3.36, height 4.2

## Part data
C1 C2 C3 C4 C5 C6 C7 C8 C9 C10 C11 C12 C14 C15 C16 C17 C21 C22 C23 C37: "CAP, CERM, 1 μF, 16 V,+/- 10%, X7R, 0603", Cap_Case=0603, Manufacturer=MuRata, Supplier Part Number 1=490-10734-1-ND, TempCo=X7R, Tolerance_%=10, Value2=16V, ValueDisplayed=1μF
C13: "CAP, CERM, 1 μF, 35 V,+/- 10%, X7R, 0603", Cap_Case=0603, Manufacturer=TDK, Supplier Part Number 1=445-7414-1-ND, TempCo=X7R, Tolerance_%=10, Value2=35V, ValueDisplayed=1μF
C18: "CAP, CERM, 0.1 μF, 100 V,+/- 10%, X7R, AEC-Q200 Grade 1, 0805", Cap_Case=0805, Manufacturer=TDK, Supplier Part Number 1=445-5827-1-ND, TempCo=X7R, Tolerance_%=10, Value1="0.020726 ohm", Value2=100V, ValueDisplayed=0.1μF
C19: "CAP, CERM, 470 pF, 50 V,+/- 5%, C0G/NP0, AEC-Q200 Grade 1, 0603", Cap_Case=0603, Manufacturer=MuRata, Supplier Part Number 1=490-4965-1-ND, TempCo=C0G/NP0, Tolerance_%=5, Value2=50V, ValueDisplayed=470pF
C20: "CAP, CERM, 2.2 μF, 100 V,+/- 10%, X7R, 1210", Cap_Case=1210, Manufacturer=MuRata, Supplier Part Number 1=490-3385-1-ND, TempCo=X7R, Tolerance_%=10, Value1="0.007 ohm", Value2=100V, ValueDisplayed=2.2μF
C24 C25 C26: "CAP, CERM, 10 μF, 50 V,+/- 10%, X5R, 1210", Cap_Case=1210, Manufacturer=TDK, Supplier Part Number 1=445-9074-6-ND, TempCo=X5R, Tolerance_%=10, Value2=50V, ValueDisplayed=10μF
C27 C28 C29: "CAP, CERM, 4700 pF, 50 V,+/- 10%, X7R, AEC-Q200 Grade 1, 0603", Cap_Case=0603, Manufacturer=MuRata, Supplier Part Number 1=490-4932-1-ND, TempCo=X7R, Tolerance_%=10, Value2=50V, ValueDisplayed=4700pF
C30 C34 C35 C44 C47: "CAP, CERM, 4.7 μF, 16 V,+/- 10%, X5R, 0603", Cap_Case=0603, Manufacturer=MuRata, Supplier Part Number 1=490-10481-1-ND, TempCo=X5R, Tolerance_%=10, Value2=16V, ValueDisplayed=4.7μF
C31 C46: "CAP, CERM, 10 μF, 16 V,+/- 10%, X7R, 0805", Cap_Case=0805, Manufacturer="Samsung Electro-Mechanics", Supplier Part Number 1=1276-2872-1-ND, TempCo=X7R, Tolerance_%=10, Value2=16V, ValueDisplayed=10μF
C32 C40: "CAP, CERM, 2.2 μF, 10 V,+/- 10%, X7R, 0603", Cap_Case=0603, Manufacturer=MuRata, Supplier Part Number 1=490-4520-1-ND, TempCo=X7R, Tolerance_%=10, Value1="0.009 ohm", Value2=10V, ValueDisplayed=2.2μF
C33 C39 C42: "CAP, CERM, 0.1 μF, 16 V,+/- 10%, X7R, 0603", Cap_Case=0603, Manufacturer=MuRata, Supplier Part Number 1=490-1532-1-ND, TempCo=X7R, Tolerance_%=10, Value2=16V, ValueDisplayed=0.1μF
C36 C41 C43 C45 C54 C55 C56 C57 C58 C60 C61: "CAP, CERM, 0.1 μF, 50 V,+/- 10%, X7R, 0603", Cap_Case=0603, Manufacturer=MuRata, Supplier Part Number 1=490-1519-1-ND, TempCo=X7R, Tolerance_%=10, Value2=50V, ValueDisplayed=0.1μF
C38: "CAP, CERM, 1000 pF, 50 V,+/- 5%, C0G/NP0, 0603", Cap_Case=0603, Manufacturer=MuRata, Supplier Part Number 1=490-1451-1-ND, TempCo=C0G/NP0, Tolerance_%=5, Value2=50V, ValueDisplayed=1000pF
C48: "CAP, CERM, 0.01 μF, 100 V,+/- 10%, X7R, 0603", Cap_Case=0603, Manufacturer=MuRata, Supplier Part Number 1=GRM188R72A103KA01D-ND, TempCo=X7R, Tolerance_%=10, Value2=100V, ValueDisplayed=0.01μF
C49: "CAP, CERM, 2.2 μF, 35 V,+/- 10%, X7R, 0805", Cap_Case=0805, Manufacturer=TDK, Supplier Part Number 1=445-14547-1-ND, TempCo=X7R, Tolerance_%=10, Value2=35V, ValueDisplayed=2.2μF
C50: "CAP, CERM, 220 pF, 50 V,+/- 10%, X7R, 0603", Cap_Case=0603, Manufacturer=MuRata, Supplier Part Number 1=490-1483-1-ND, TempCo=X7R, Tolerance_%=10, Value2=50V, ValueDisplayed=220pF
C51: "CAP, CERM, 2200 pF, 100 V,+/- 5%, X7R, 0603", Cap_Case=0603, Manufacturer=AVX, Supplier Part Number 1=478-3705-1-ND, TempCo=X7R, Tolerance_%=5, Value1="0.192 ohm", Value2=100V, ValueDisplayed=2200pF
C52 C53 C68 C69 C70 C71: "CAP, CERM, 0.1 μF, 100 V,+/- 10%, X7R, 0603", Cap_Case=0603, Manufacturer=MuRata, Supplier Part Number 1=490-3285-1-ND, TempCo=X7R, Tolerance_%=10, Value2=100V, ValueDisplayed=0.1μF
C59: "CAP, CERM, 4.7 μF, 100 V,+/- 10%, X7S, 1210", Cap_Case=1210, Manufacturer=TDK, Supplier Part Number 1=445-8912-1-ND, TempCo=X7S, Tolerance_%=10, Value2=100V, ValueDisplayed=4.7μF
C62: "NC", Cap_Case=0603, Manufacturer=MuRata, Supplier Part Number 1=490-1421-1-ND, TempCo=C0G/NP0, Tolerance_%=5, Value2=50V
C63: "CAP, CERM, 2200 pF, 50 V,+/- 5%, C0G/NP0, 0603", Cap_Case=0603, Manufacturer=MuRata, Supplier Part Number 1=490-1459-1-ND, TempCo=C0G/NP0, Tolerance_%=5, Value2=50V, ValueDisplayed=2200pF
C64: "CAP, CERM, 56 pF, 50 V,+/- 5%, C0G/NP0, 0603", Cap_Case=0603, Manufacturer=MuRata, Supplier Part Number 1=490-1421-1-ND, TempCo=C0G/NP0, Tolerance_%=5, Value2=50V, ValueDisplayed=56pF
C65: "CAP, CERM, 3300 pF, 50 V,+/- 10%, X7R, 0603", Cap_Case=0603, Manufacturer=MuRata, Supplier Part Number 1=490-1503-1-ND, TempCo=X7R, Tolerance_%=10, Value2=50V, ValueDisplayed=3300pF
C66 C67: "CAP, CERM, 4.7 μF, 16 V,+/- 10%, X7R, 0805", Cap_Case=0805, Manufacturer=MuRata, Supplier Part Number 1=490-4522-1-ND, TempCo=X7R, Tolerance_%=10, Value1="0.006 ohm", Value2=16V, ValueDisplayed=4.7μF
D1 D28 D29 D35: "Diode, Zener, 3.6 V, 500 mW, SOD-123", Manufacturer="ON Semiconductor", Power_W=0.5, Supplier Part Number 1=MMSZ4685T1GOSCT-ND, Value1=0.5W
D2 D3 D4 D5 D6 D7 D8 D9 D10 D12 D13 D14 D15: "Diode, Zener, 5.6 V, 300 mW, SOD-523", Manufacturer="Diodes Inc.", Power_W=0.3, Supplier Part Number 1=BZT52C5V6TDICT-ND, Value1=0.3W
D11 D17 D18 D20 D42: "Diode, Ultrafast, 100 V, 0.15 A, SOD-123", Manufacturer="Diodes Inc.", Supplier Part Number 1=1N4148W-FDICT-ND, Value1=0.15A, Value2=1.25V
D16 D38: "Diode, Zener, 18 V, 500 mW, SOD-123", Manufacturer="Diodes Inc.", Power_W=0.5, Supplier Part Number 1=MMSZ5248B-FDICT-ND, Value1=0.5W
D19 D22: "Diode, Super Barrier Rectifier, 20 V, 0.2 A, SOD-523", Manufacturer="Diodes Inc.", Supplier Part Number 1=SBR0220T5-7DICT-ND, Value1=0.2A, Value2=0.43V
D21: "Diode, Zener, 3.3 V, 200 mW, SOD-323", Manufacturer="Diodes Inc.", Power_W=0.2, Supplier Part Number 1=MMSZ5226BS-FDICT-ND, Value1=0.2W
D23 D24 D25 D26 D27: "LED, Red, SMD", Color=Red, Manufacturer="Wurth Elektronik", Power_TotalModule=0.072, Supplier Part Number 1=732-4978-1-ND, Value1=0.072W, Value2=2V
D30 D31 D45 D46: "Diode, Schottky, 20 V, 0.5 A, SOD-123", Manufacturer="ON Semiconductor", Supplier Part Number 1=MBR0520LT1GOSCT-ND, Value1=0.5A, Value2=0.385V
D32: library part NUP2105LT1G, "Diode, TVS, Bi, 24 V, SOT-23", Manufacturer="ON Semiconductor", Power_W=0.35, Supplier Part Number 1=NUP2105LT1GOSCT-ND, Value1=0.35W
D33 D39 D41: "Diode, Schottky, 100 V, 0.15 A, SOD-123", Manufacturer="Diodes Inc.", Supplier Part Number 1=BAT46W-7FDICT-ND, Value1=0.15A, Value2=0.6V
D34: "Diode, Zener, 5.1 V, 500 mW, SOD-123", Manufacturer="Diodes Inc.", Power_W=0.5, Supplier Part Number 1=MMSZ5231B-FDICT-ND, Value1=0.5W
D36 D37 D40 D43 D47: "Diode, Zener, 16 V, 500 mW, SOD-123", Manufacturer="Diodes Inc.", Power_W=0.5, Supplier Part Number 1=MMSZ5246B-FDICT-ND, Value1=0.5W
D44: library part SMBJ60A-13-F, "Diode, TVS, Uni, 60 V, 96.8 Vc, SMB", Manufacturer="Diodes Inc.", Power_W=5, Supplier Part Number 1=SMBJ60A-FDICT-ND, Value1=5W
D48: "Diode, TVS, Uni, 60 V, 96.8 Vc, SMB", Manufacturer="Diodes Inc.", Power_W=5, Supplier Part Number 1=SMBJ60A-FDICT-ND, Value1=5W
F1: library part SFK-5030, "Fuse, 30 A, SMD", Irating_A=30, Manufacturer=POLYTRONICS
F2: "Fuse, 30 A, 125 VAC, 72 VDC, SMD", Irating_A=30, Manufacturer=Littelfuse, Supplier Part Number 1=F3345CT-ND
J1 J2 J6 J7: library part 8199, "TERMINAL SCREW PC 30AMP, TH", Manufacturer=Keystone, Supplier Part Number 1=36-8199-ND
J3 J4 J5: "Header, 2.54mm, 2x1, Vertical, TH", Manufacturer=Molex, Supplier Part Number 1=WM4200-ND
L1: "Inductor, Shielded Drum Core, Ferrite, 68 μH, 1.1 A, 0.275 ohm, SMD", Manufacturer="Wurth Elektronik", Supplier Part Number 1=732-2983-1-ND, Value1="0.275 ohm", Value2=1.1A, ValueDisplayed=68μH
L2 L3 L4 L5 L6 L7: "Ferrite Bead, 600 ohm @ 100 MHz, 0.2 A, 0603", Manufacturer="Wurth Elektronik", Supplier Part Number 1=732-1583-1-ND, Value1="0.45 ohm", Value2=0.2A, ValueDisplayed="600 ohm"
Logo1: library part CMP-0074836-1, "IEC 61010-1 Caution Warning"
Logo2: library part CMP-0074847-1, "FCC_disclaimer"
P1: "Header, 2-Pin, Dual row"
P2 P3: "Header, 4-Pin"
P4 P5: "Header, 14-Pin"
P6: "Header, 2-Pin"
Q1 Q2 Q3 Q4 Q5 Q6 Q7 Q8 Q9 Q10 Q11 Q12 Q13: "MOSFET, N-CH, 20 V, 2.8 A, AEC-Q101, SOT-23", Alternate Manufacturer=None, Manufacturer="Diodes Inc.", Supplier Part Number 1=DMG2302UK-7DICT-ND, Value1="0.09 ohm", Value2="1.4 nC"
Q14 Q17 Q21 Q24 Q25: "MOSFET, N-CH, 100 V, 0.17 A, SOT-23", Alternate Manufacturer=None, Manufacturer="Fairchild Semiconductor", Supplier Part Number 1=BSS123NCT-ND, Value1="10 ohm", Value2="1.8 nC"
Q15 Q16 Q26 Q31: "MOSFET, P-CH, -100 V, -0.6 A, SOT-23", Alternate Manufacturer=None, Manufacturer="Diodes Inc.", Supplier Part Number 1=ZXMP10A13FCT-ND, Value1="1 ohm", Value2="3.5 nC"
Q18 Q19: "MOSFET, P-CH, -20 V, -2.4 A, SOT-23", Alternate Manufacturer=None, Manufacturer="Fairchild Semiconductor", Supplier Part Number 1=FDN302PCT-ND, Value1="0.055 ohm", Value2="9 nC"
Q20 Q27: "MOSFET, N-CH, 60 V, 115 A, SOT-23", Alternate Manufacturer=None, Manufacturer="Fairchild Semiconductor", Supplier Part Number 1=2N7002NCT-ND, Value1="? ohm", Value2="? nC"
Q22: "MOSFET, P-CH, -50 V, -0.13 A, SOT-23", Alternate Manufacturer=None, Manufacturer="Diodes Inc.", Supplier Part Number 1=BSS84-FDICT-ND, Value1="? ohm", Value2="? nC"
Q23: "MOSFET, N-CH, 60 V, 0.115 A, SOT-323", Alternate Manufacturer=None, Manufacturer="Diodes Inc.", Supplier Part Number 1=2N7002W-FDICT-ND, Value1="7.5 ohm", Value2="? nC"
Q28 Q29 Q30 Q32 Q33 Q34: "MOSFET, N-CH, 100 V, 200 A, KTT0002A (TO-263-2)", Alternate Manufacturer=None, Manufacturer="Texas Instruments", Supplier Part Number 1=296-41136-1-ND, Value1="? ohm", Value2="118 nC"
R1 R2 R3 R4 R5 R6 R7 R8 R9 R10 R22 R23 R24 R25 R26 R27 R28 R29 R39 R40 R41 R42 R43 R44 R45 R46: "RES, 80.6, 1%, 0.25 W, 1206", Manufacturer=Vishay-Dale, Power_W=0.25, Supplier Part Number 1=541-80.6FCT-ND, TempCo="100 ppm/C", Tolerance_%=1, Value1=1%, Value2=0.25W, Value_Code=80R6, ValueDisplayed=80.6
